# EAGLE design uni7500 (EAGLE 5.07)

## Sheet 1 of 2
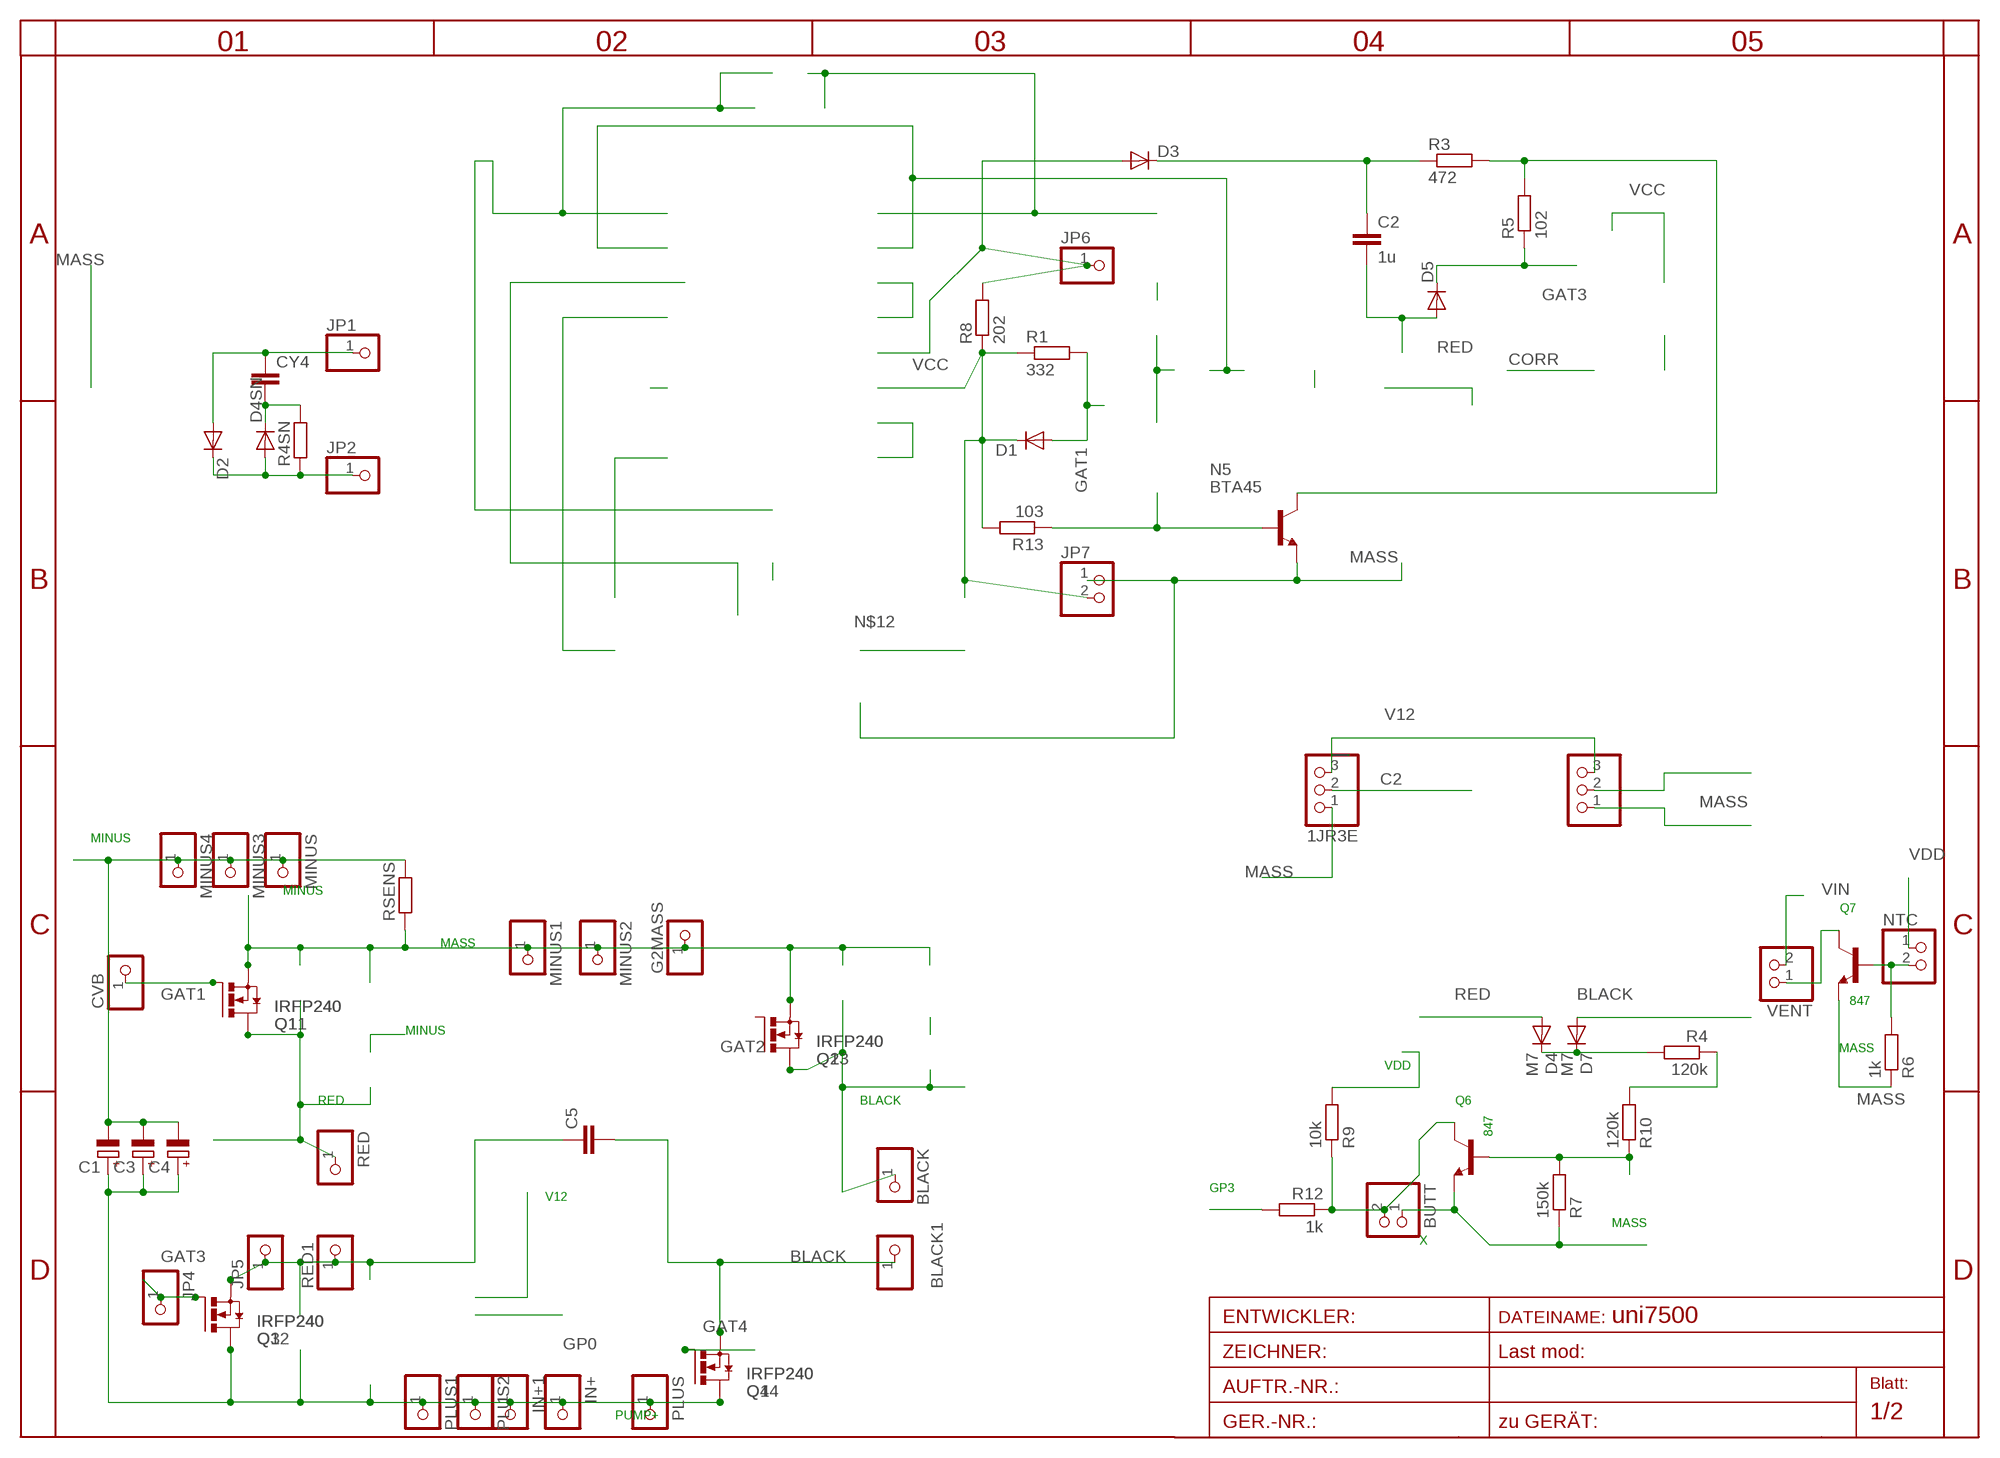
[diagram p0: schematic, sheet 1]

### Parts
1JR3E  PINHD-1X3  [1X03]
2JR4E3  PINHD-1X3  [1X03]
BLACK  PINHD-1X12MM3  [1X2MM3]
BLACK1  PINHD-1X12MM3  [1X2MM3]
BUTT  PINHD-1X2STR  [1X02]
C1  CPOL-EUE5-13  [E5-13]
C2  1u  C-EUC1206  [C1206]
C3  CPOL-EUE5-13  [E5-13]
C4  CPOL-EUE5-13  [E5-13]
C5  C-EU075-032X103  [C075-032X103]
CVB  PINHD-1X11MM0  [1X1MM0]
CY4  CXXC10B5  [XC10B5]
D1  DIODE-MINIMELF  [MINIMELF]
D2  DIODE-SMC  [SMC]
D3  DIODE-SMA-DO214  [SMA-DO214AC]
D4  M7  1N4004DO41-10  [DO41-10]
D4SN  DIODE-P1-10  [P1-10]
D5  DIODE-MINIMELF  [MINIMELF]
D7  M7  1N4004DO41-10  [DO41-10]
G2MASS  PINHD-1X11MM0  [1X1MM0]
IN+  PINHD-1X12MM3  [1X2MM3]
IN+1  PINHD-1X12MM3  [1X2MM3]
JP1  PINHD-1X11MM0  [1X1MM0]
JP2  PINHD-1X11MM0  [1X1MM0]
JP4  PINHD-1X11MM0  [1X1MM0]
JP5  PINHD-1X11MM0  [1X1MM0]
JP6  PINHD-1X11X0.4  [1X01]
JP7  PINHD-1X2STR  [1X02]
MINUS  PINHD-1X12MM3  [1X2MM3]
MINUS1  PINHD-1X12MM3  [1X2MM3]
MINUS2  PINHD-1X12MM3  [1X2MM3]
MINUS3  PINHD-1X12MM3  [1X2MM3]
MINUS4  PINHD-1X12MM3  [1X2MM3]
N5  BTA45  SMBTA45HV  [SOT23HV]
NTC  PINHD-1X2STR  [1X02]
PLUS  PINHD-1X12MM3  [1X2MM3]
PLUS1  PINHD-1X12MM3  [1X2MM3]
PLUS2  PINHD-1X12MM3  [1X2MM3]
Q1  IRFP240  [TO247BV]
Q2  IRFP240  [TO247BV]
Q3  IRFP240  [TO247BV]
Q4  IRFP240  [TO247BV]
Q6  847  BC847ALT1SMD  [SOT23]
Q7  847  BC847ALT1SMD  [SOT23]
Q11  IRFP240  [TO247BV]
Q12  IRFP240  [TO247BV]
Q13  IRFP240  [TO247BV]
Q14  IRFP240  [TO247BV]
R1  332  R-EU_R0805  [R0805]
R3  472  R-EU_R0805  [R0805]
R4  120k  R-EU_R1210  [R1210]
R4SN  R-EU_0207/10  [0207/10]
R5  102  R-EU_R1206  [R1206]
R6  1k  R-EU_R0805  [R0805]
R7  150k  R-EU_R0805  [R0805]
R8  202  R-EU_R0805  [R0805]
R9  10k  R-EU_R0805  [R0805]
R10  120k  R-EU_R1210  [R1210]
R12  1k  R-EU_R0805  [R0805]
R13  103  R-EU_0207/15  [0207/15]
RED  PINHD-1X12MM3  [1X2MM3]
RED1  PINHD-1X12MM3  [1X2MM3]
RSENS  R-EU_0204/7  [0204/7]
VENT  PINHD-1X2STR  [1X02]

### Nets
BLACK: BLACK1.1 BLACK.1 C5.2 D7.A Q2.D Q4.S Q13.D Q14.S
C1: 2JR4E3.2 ; also sheet 2
C2: 1JR3E.2 D1.C JP7.2 R1.1 R8.1 R13.2 ; also sheet 2
DRAIN: D2.C D4SN.A JP2.1 R4SN.1
GAT1: CVB.1 D1.A Q1.G Q11.G R1.2
GAT2: Q2.G Q13.G
GAT3: D5.C JP4.1 Q3.G Q12.G R5.1
GAT4: Q4.G Q14.G
GP3: R12.2 ; also sheet 2
MASS: 1JR3E.1 2JR4E3.1 BUTT.1 G2MASS.1 JP7.1 MINUS1.1 MINUS2.1 N5.2(E) Q1.S Q2.S Q6.2(E) Q7.2(E) Q11.S Q13.S R6.1 R7.1 RSENS.1 ; also sheet 2
MINUS: C1.- C3.- C4.- MINUS3.1 MINUS4.1 MINUS.1 RSENS.2
N$1: D4.C D7.C R4.2
N$4: C2.1 D3.K(C) R3.1
N$5: Q6.1(B) R7.2 R10.1
N$7: R4.1 R10.2
N$8: N5.3(C) R3.2 R5.2
N$9: NTC.2 Q7.1(B) R6.2
N$10: Q7.3(C) VENT.1
N$17: N5.1(B) R13.1
PUMP+: C1.+ C3.+ C4.+ IN+1.1 IN+.1 PLUS1.1 PLUS2.1 PLUS.1 Q3.D Q4.D Q12.D Q14.D ; also sheet 2
RED: C2.2 C5.1 D4.A D5.A JP5.1 Q1.D Q3.S Q11.D Q12.S RED1.1 RED.1
SNUB2: CY4.2 D4SN.C R4SN.2
SOURCE: CY4.1 D2.A JP1.1
V12: 1JR3E.3 2JR4E3.3
VCC: D3.A JP6.1 R8.2
VDD: NTC.1 R9.2 ; also sheet 2
VIN: VENT.2
X: BUTT.2 Q6.3(C) R9.1 R12.1

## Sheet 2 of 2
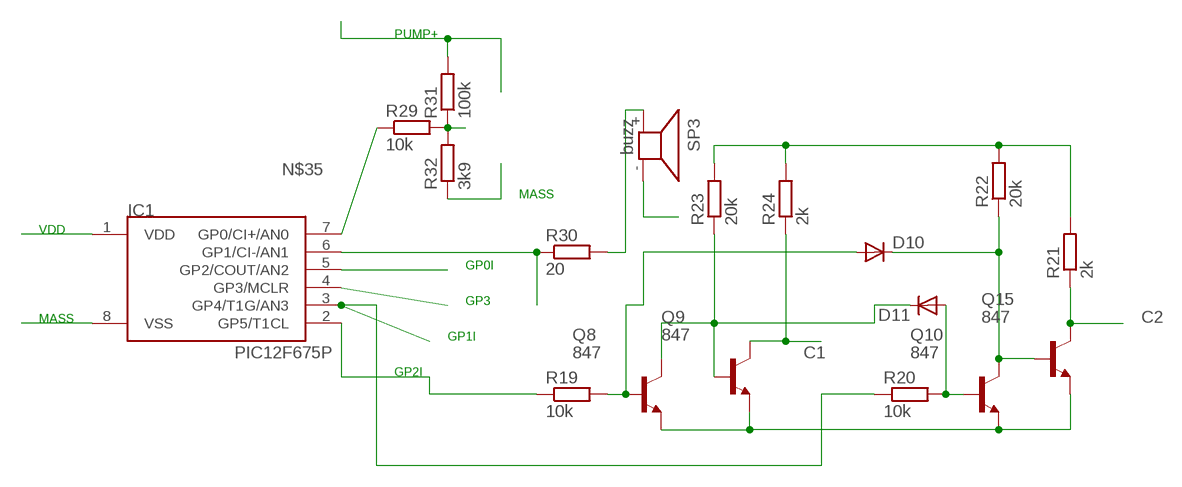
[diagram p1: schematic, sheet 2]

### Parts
D10  DIODE-MINIMELF  [MINIMELF]
D11  DIODE-MINIMELF  [MINIMELF]
IC1  PIC12F675P  [DIL8]
Q8  847  BC847ALT1SMD  [SOT23]
Q9  847  BC847ALT1SMD  [SOT23]
Q10  847  BC847ALT1SMD  [SOT23]
Q15  847  BC847ALT1SMD  [SOT23]
R19  10k  R-EU_R0805  [R0805]
R20  10k  R-EU_R0805  [R0805]
R21  2k  R-EU_R0805  [R0805]
R22  20k  R-EU_R0805  [R0805]
R23  20k  R-EU_R0805  [R0805]
R24  2k  R-EU_R0805  [R0805]
R29  10k  R-EU_R0805  [R0805]
R30  20  R-EU_R0805  [R0805]
R31  100k  R-EU_0207/25  [0207/25]
R32  3k9  R-EU_R0805  [R0805]
SP3  buzz  KSS12017MM  [KSS1202]

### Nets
C1: Q9.3(C) R24.1 ; also sheet 1
C2: Q15.3(C) R21.1 ; also sheet 1
GP0I: IC1.5(GP2/COUT/AN2)
GP1I: IC1.3(GP4/T1G/AN3) R20.1
GP2I: IC1.2(GP5/T1CL) R19.1
GP3: IC1.4(GP3/MCLR) ; also sheet 1
MASS: IC1.8(VSS) R32.1 SP3.- ; also sheet 1
N$22: D11.A Q10.1(B) R20.2
N$24: R30.2 SP3.+
N$26: D11.C Q8.3(C) Q9.1(B) R23.1
N$27: D10.C Q10.3(C) Q15.1(B) R22.1
N$28: D10.A Q8.1(B) R19.2
N$30: Q8.2(E) Q9.2(E) Q10.2(E) Q15.2(E)
N$31: IC1.6(GP1/CI-/AN1) R30.1
N$32: R21.2 R22.2 R23.2 R24.2
N$34: R29.2 R31.1 R32.2
N$35: IC1.7(GP0/CI+/AN0) R29.1
PUMP+: R31.2 ; also sheet 1
VDD: IC1.1(VDD) ; also sheet 1

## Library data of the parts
1JR3E 2JR4E3 = pinhead:PINHD-1X3: PIN HEADER
BLACK BLACK1 CVB G2MASS IN+ IN+1 JP1 JP2 JP4-JP6 MINUS MINUS1-MINUS4 PLUS PLUS1 PLUS2 RED RED1 = pinhead:PINHD-1X1: PIN HEADER
BUTT JP7 NTC VENT = pinhead:PINHD-1X2: PIN HEADER
C1 C3 C4 = rcl:CPOL-EU: POLARIZED CAPACITOR, European symbol
C2 C5 = rcl:C-EU: CAPACITOR, European symbol
CY4 = rcl:CX: X CAPACITOR
D1-D3 D4SN D5 D10 D11 = diode:DIODE-: DIODE
D4 D7 = diode:1N4004: DIODE
IC1 = microchip-5:PIC12F6*: uPC nW 1k Program Flash memory 2x Timer Comparator 10b A/D converter/ 4xIN
N5 = transistor-npn:SMBTA45
Q1-Q4 Q11-Q14 = transistor-power:IRFP240: HEXFET Power MosFet Source: http://www.irf.com/
Q6-Q10 Q15 = transistor-npn:BC847*: NPN Transistor
R1 R3 R4 R4SN R5-R10 R12 R13 RSENS = rcl:R-EU_: RESISTOR, European symbol
R19-R24 R29-R32 = rcl-2:R-EU_: RESISTOR, European symbol
SP3 = buzzer:KSS1201: SPEAKER

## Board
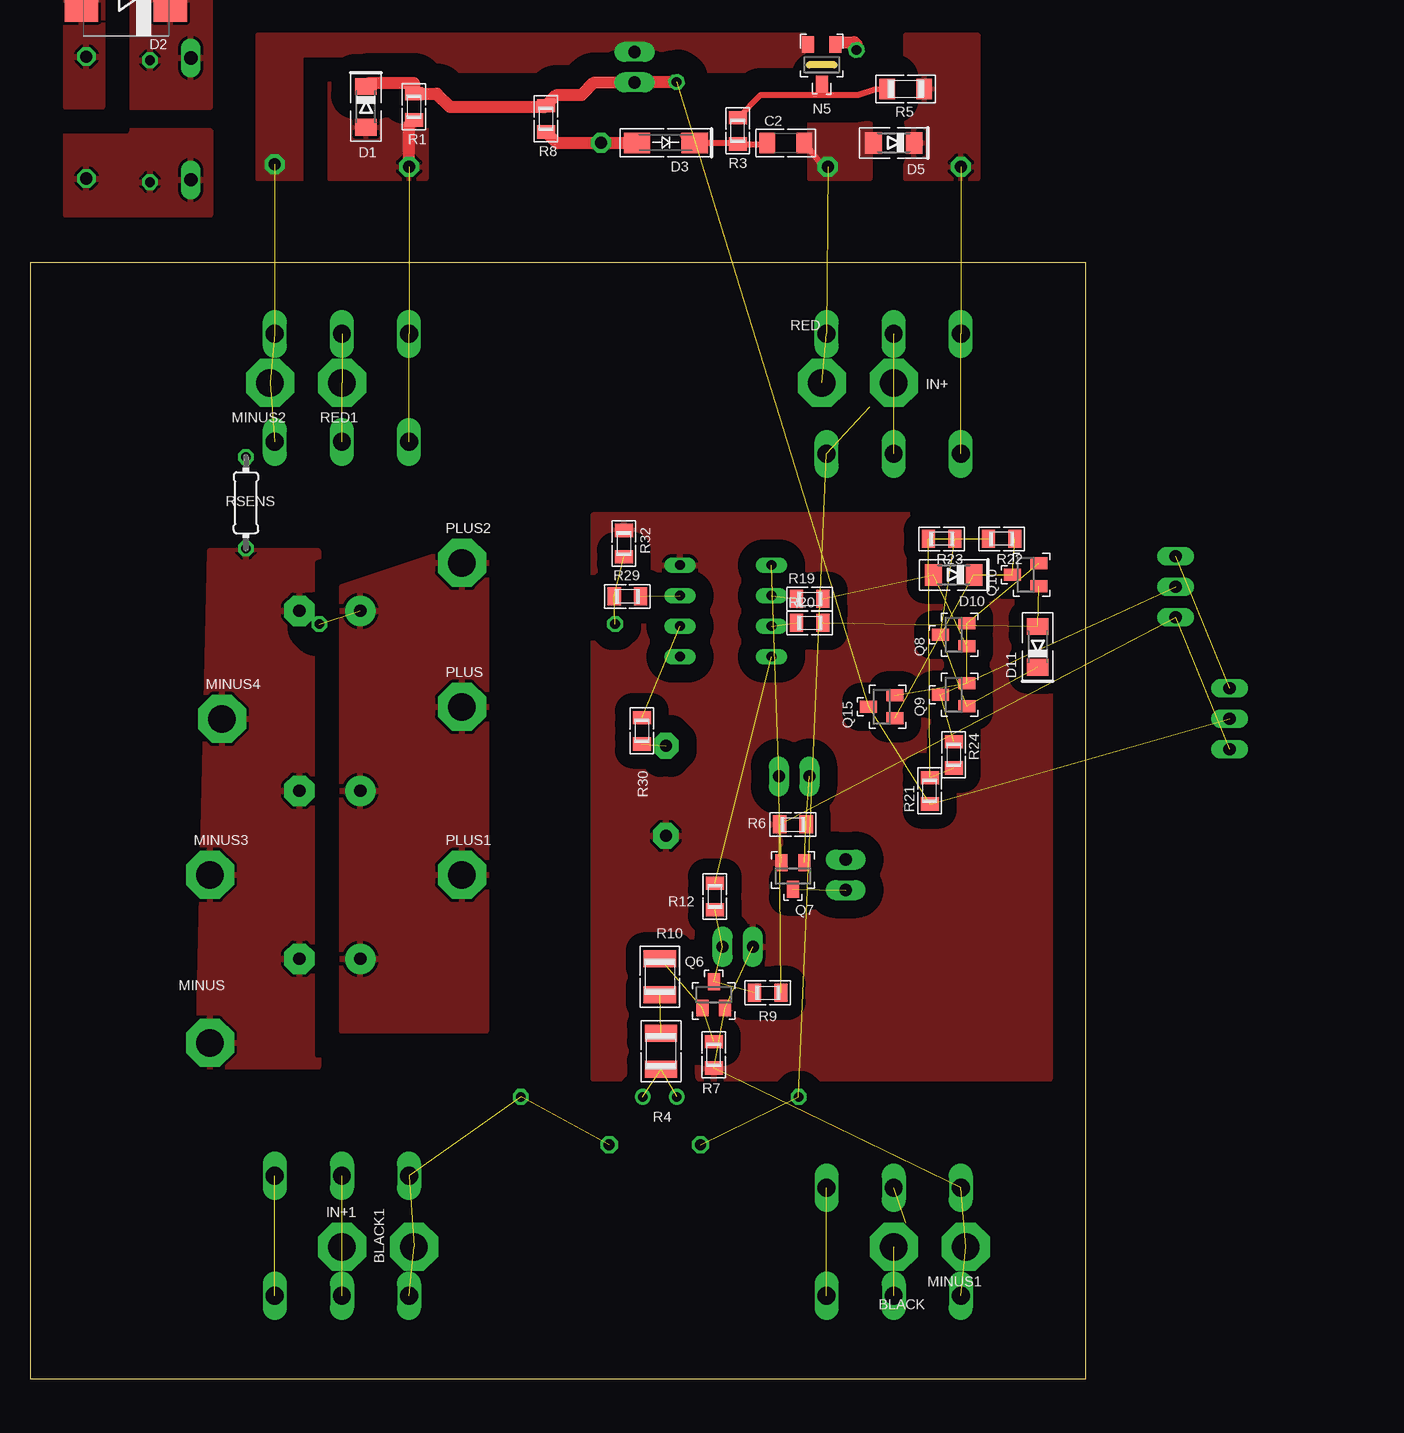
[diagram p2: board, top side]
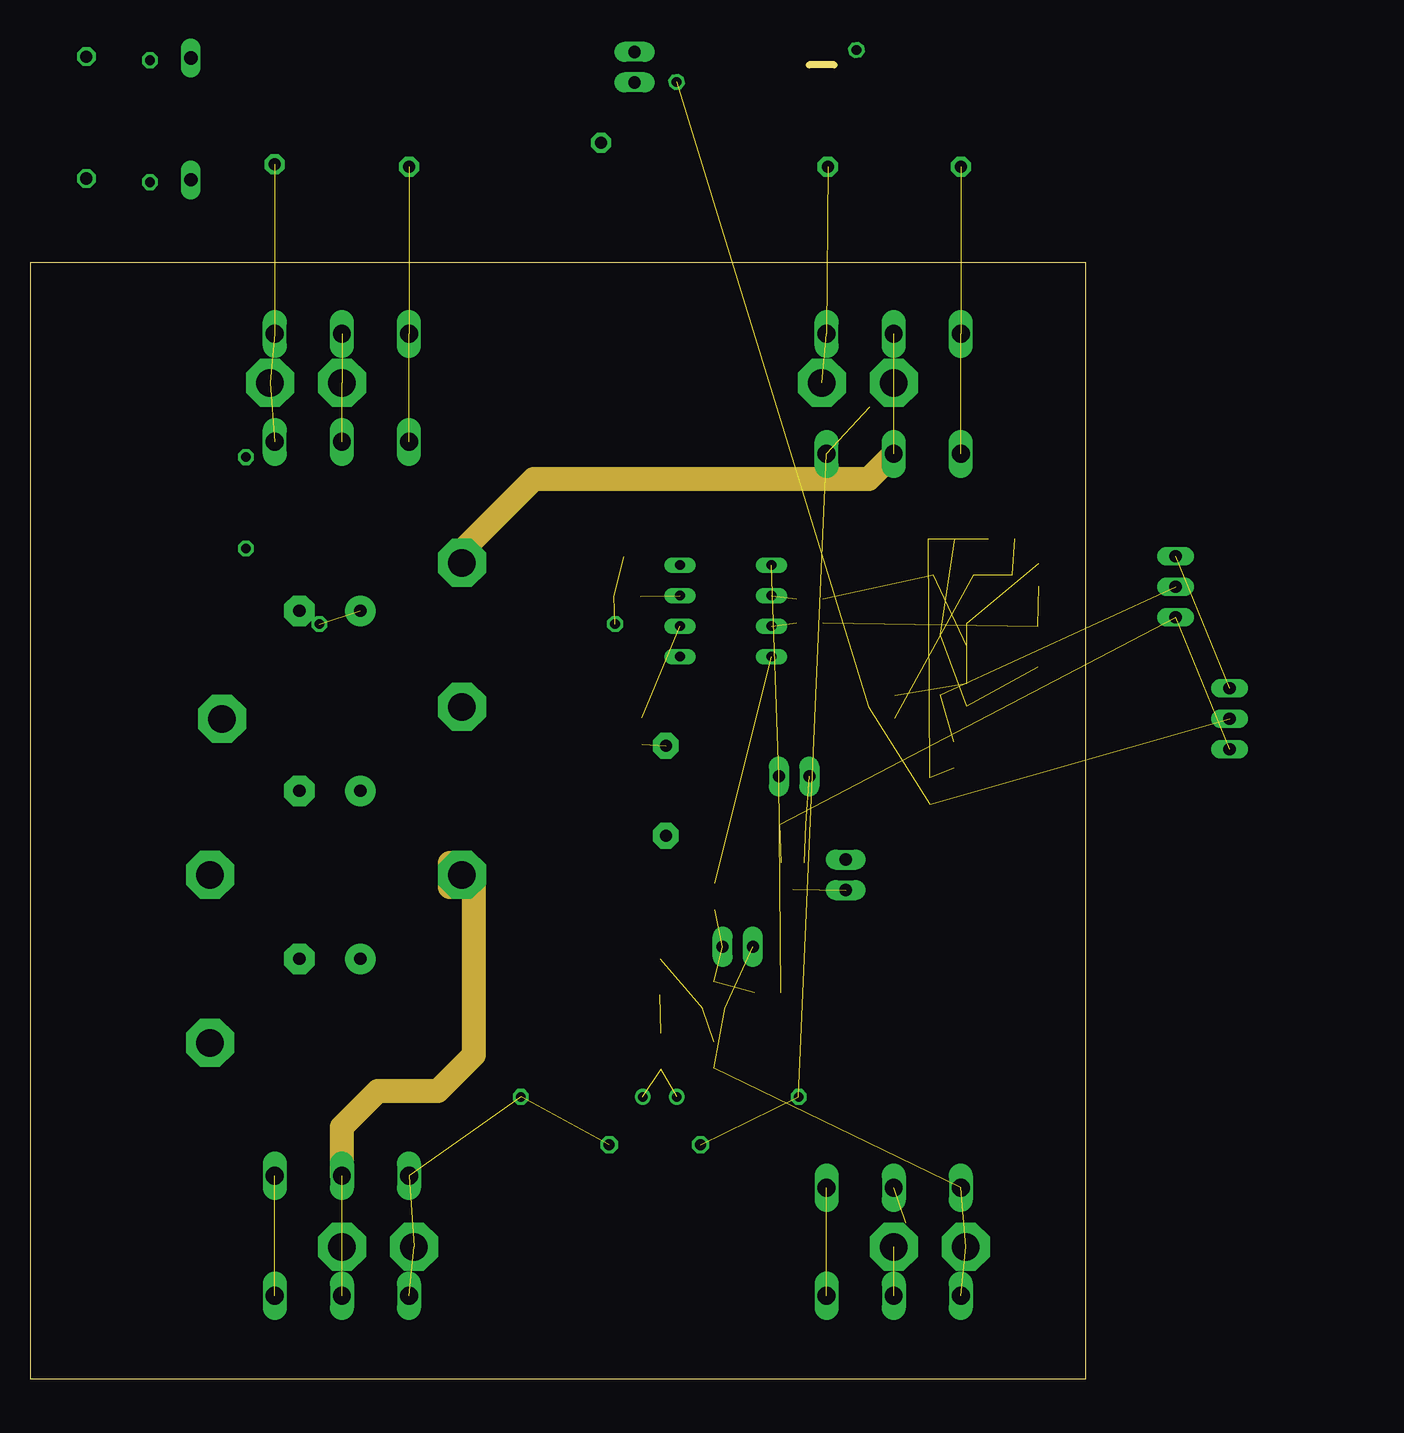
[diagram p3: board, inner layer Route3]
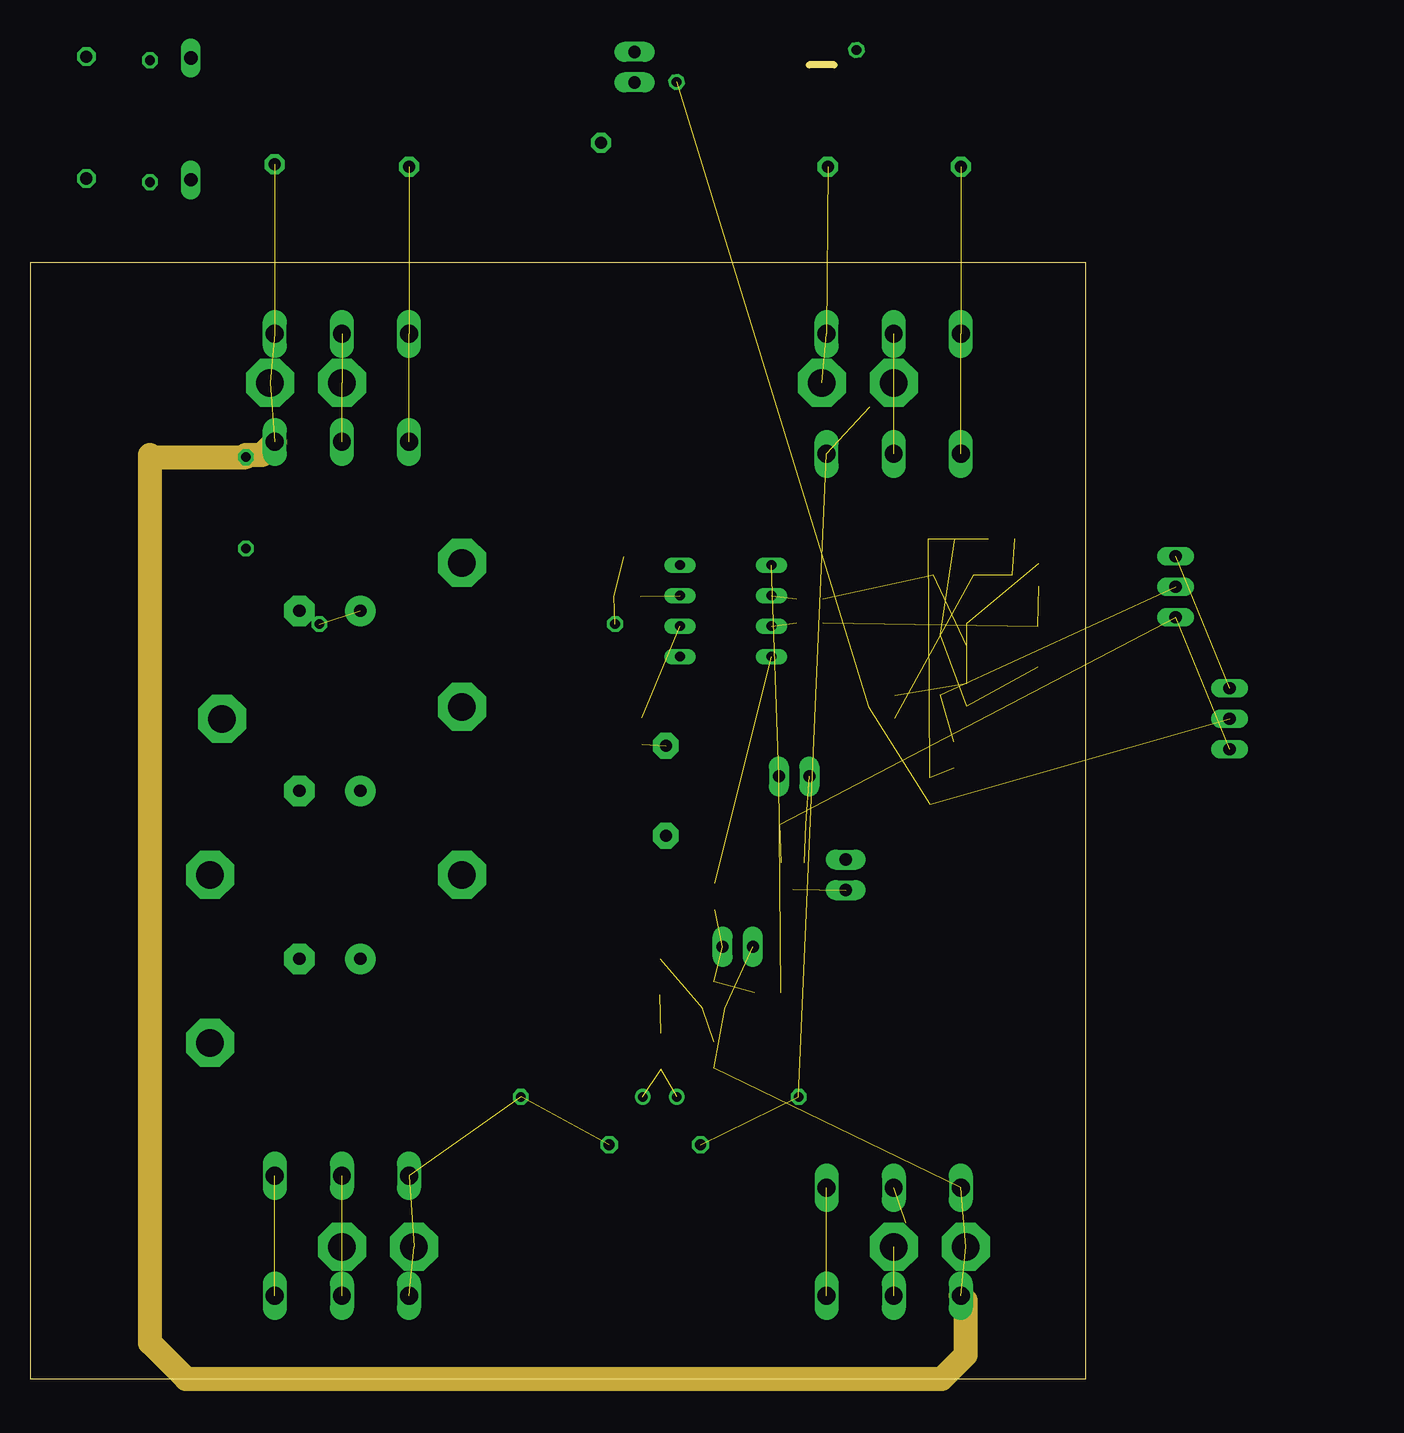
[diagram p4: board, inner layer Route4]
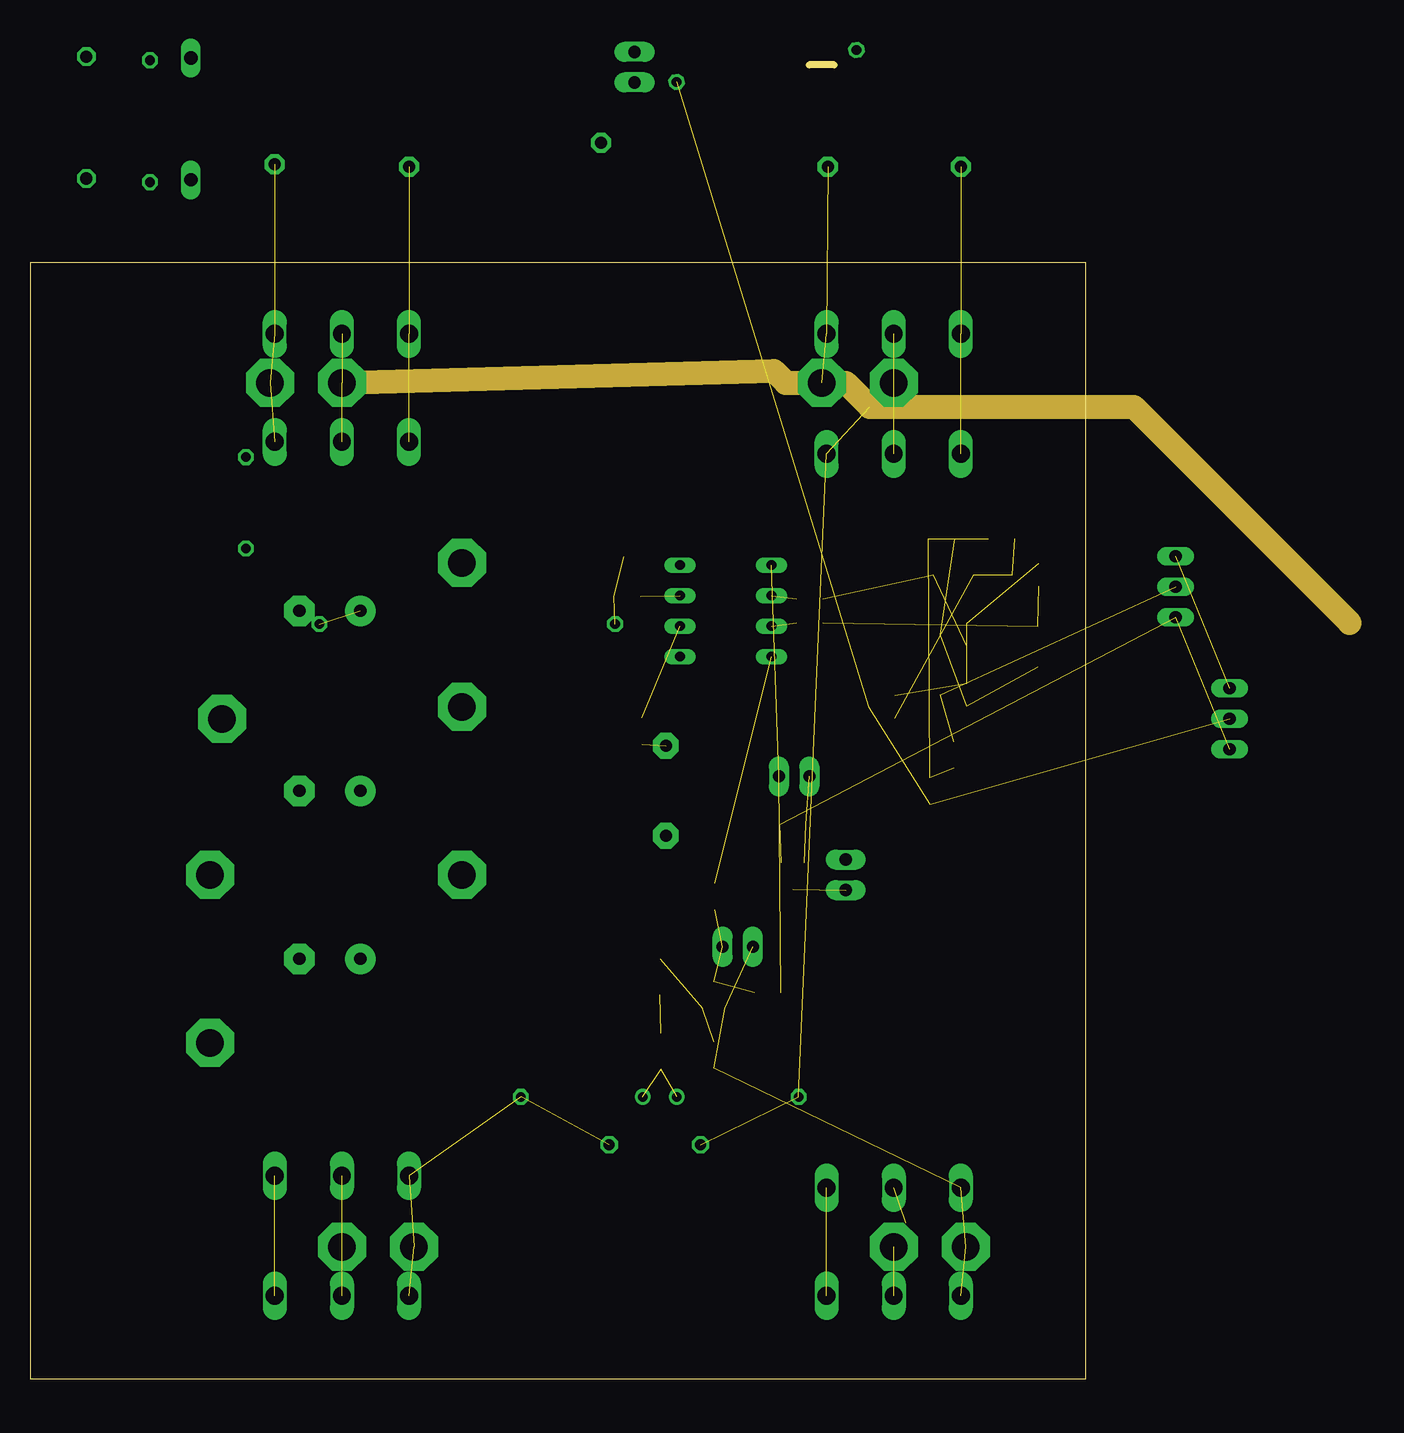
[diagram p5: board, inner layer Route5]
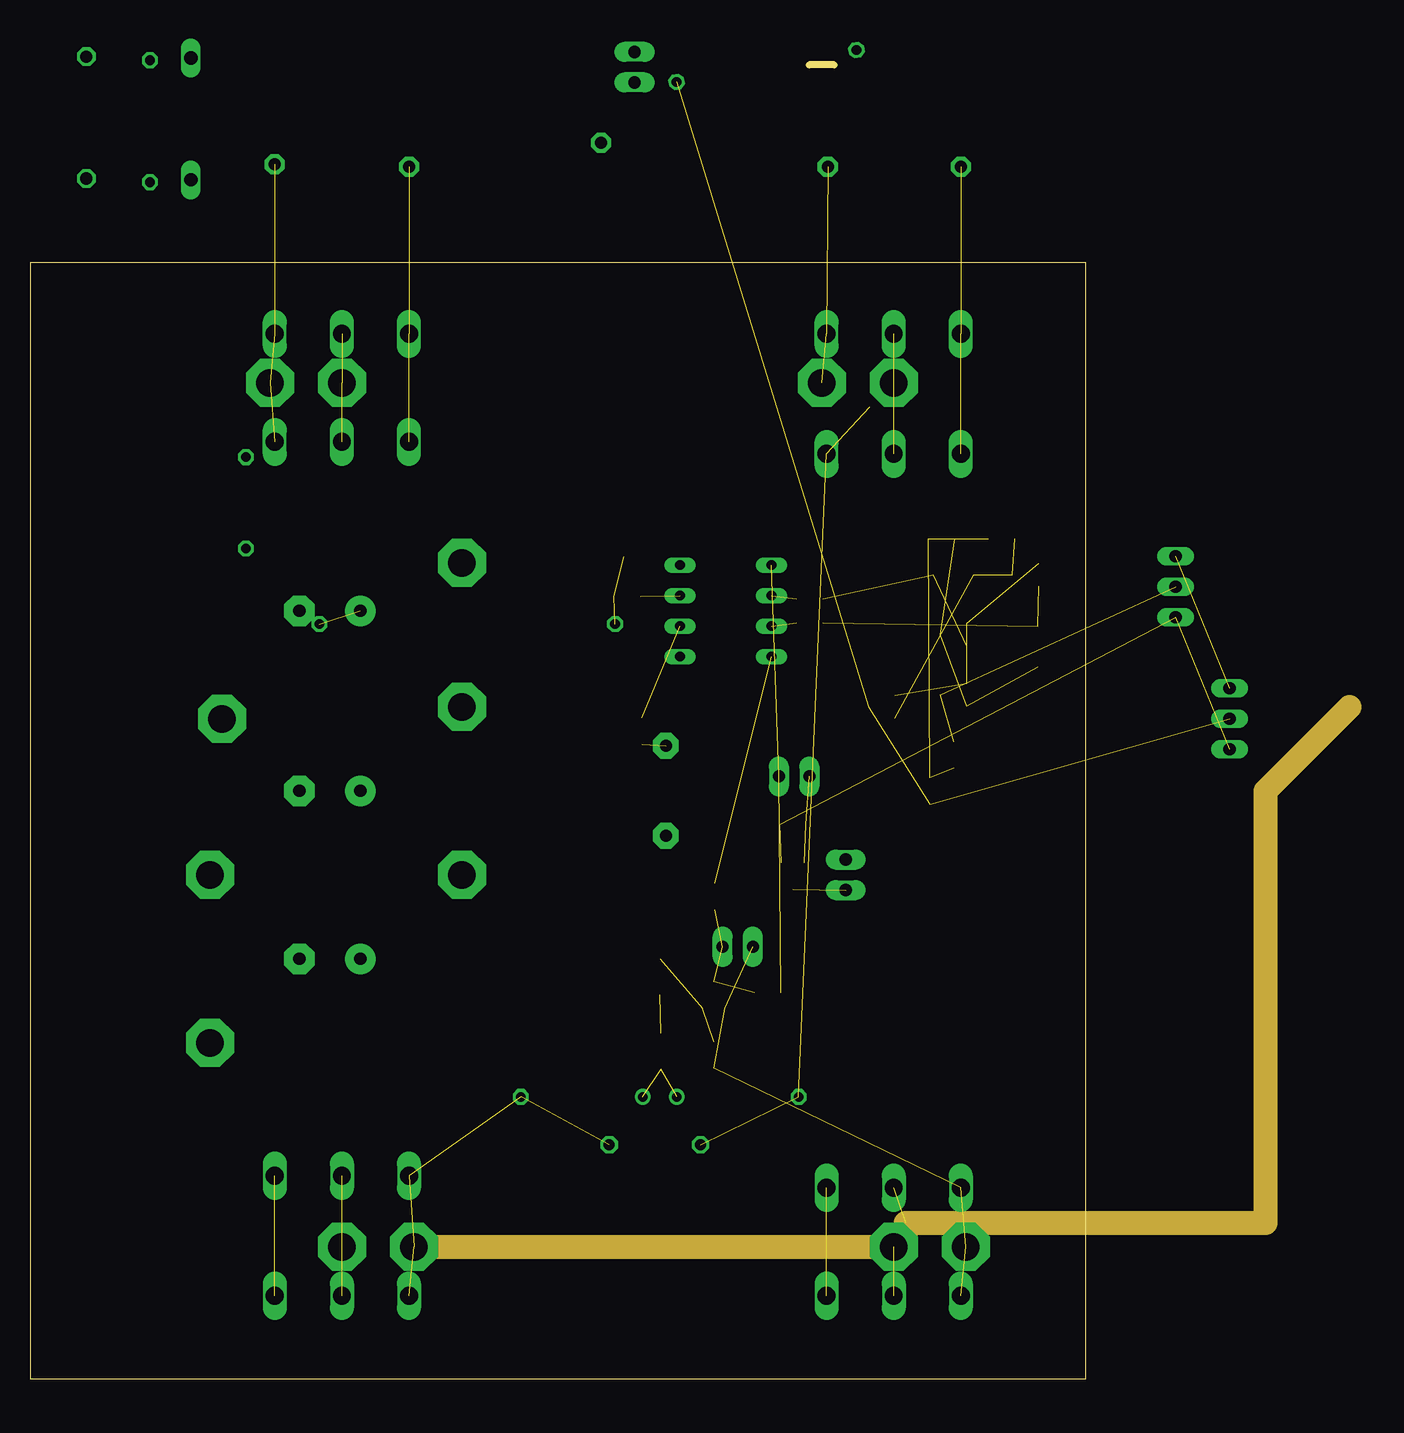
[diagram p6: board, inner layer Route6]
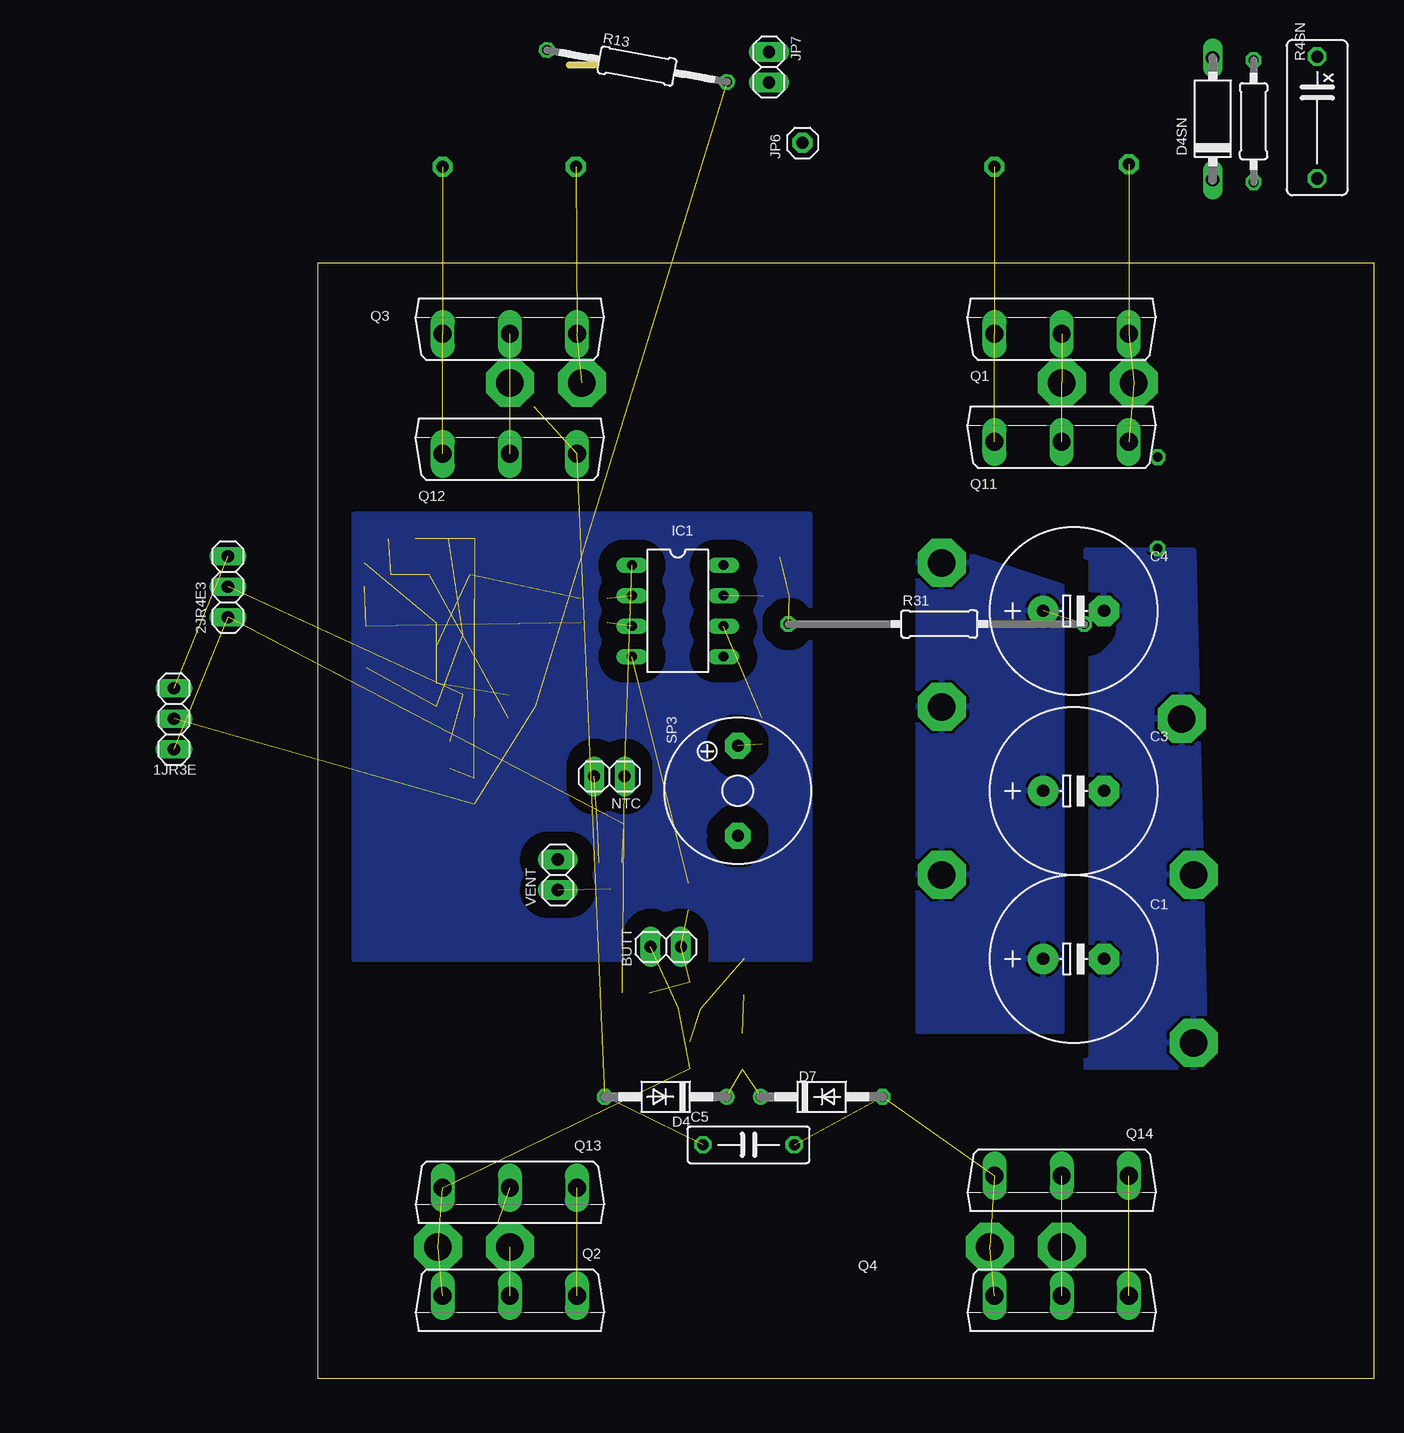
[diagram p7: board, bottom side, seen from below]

Size 88 x 93 mm. Coordinates in mm from the lower left corner, seen from the top.
Outline: 0,0 88,0 88,93 0,93 0,0
Copper layers (1*16): Top 0.035mm / dielectric 1.5mm / Bottom 0.035mm
Design rules "default *": minimum track width 10mil, minimum drill 20mil, track to track 8mil, track to pad 8mil, pad to pad 8mil, via to via 8mil, smd to smd 8mil, copper to edge 40mil, drill to drill 8mil, minimum pad ring 10mil, minimum via ring 8mil, stop-mask expansion 4mil, vias tented up to drill 0mil, thermal gap 10mil

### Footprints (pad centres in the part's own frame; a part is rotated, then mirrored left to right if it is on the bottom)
1X03 = drill 1.016 long: 1 -2.54,0; 2 0,0; 3 2.54,0
1X2MM3 = drill 2.3 pad 4 octagon: 1 0,0
1X02 = drill 1.016 pad 1.676 long: 1 -1.27,0; 2 1.27,0
E5-13 = drill 1.016 pad 2.54 round: + -2.54,0 | drill 1.016 pad 2.54 octagon: - 2.54,0
C1206 = smd 1.3 x 1.7: 1 -1.55,0; 2 1.55,0
C075-032X103 = drill 0.914 octagon: 1 -3.81,0; 2 3.81,0
1X1MM0 = drill 1 pad 1.676 octagon: 1 0,0
XC10B5 = drill 1.016 octagon: 1 -5.08,0; 2 5.08,0
MINIMELF = smd 1.4 x 1.8: A 1.7,0; C -1.7,0
SMC = smd 2.8 x 3.8: A 3.7,0; C -3.7,0
SMA-DO214AC = smd 2.2 x 1.7: A 2.4,0; K -2.4,0
DO41-10 = drill 0.8 octagon: A 5.08,0 | drill 0.8 round: C -5.08,0
P1-10 = drill 1.118 long: A 5.08,0; C -5.08,0
DIL8 = drill 0.8 long: 1 -3.81,-3.81; 2 -1.27,-3.81; 3 1.27,-3.81; 4 3.81,-3.81; 5 3.81,3.81; 6 1.27,3.81; 7 -1.27,3.81; 8 -3.81,3.81
1X01 = drill 1 pad 1.676 octagon: 1 0,0
SOT23HV = smd 1 x 1.4: 1 -1.15,-1.7; 2 1.15,-1.7; 3 0,1.6
TO247BV = drill 1.499 long: D 0,-2.921; G -5.588,-2.921; S 5.588,-2.921
SOT23 = smd 1 x 1.4: 1 -0.95,-1.1; 2 0.95,-1.1; 3 0,1.1
R0805 = smd 1.1 x 1.5: 1 -1.1,0; 2 1.1,0
R1210 = smd 1.4 x 2.7: 1 -1.5,0; 2 1.5,0
0207/10 = drill 0.813 octagon: 1 -5.08,0; 2 5.08,0
R1206 = smd 1.3 x 1.7: 1 -1.55,0; 2 1.55,0
0207/15 = drill 0.813 octagon: 1 -7.62,0; 2 7.62,0
0207/25 = drill 0.813 octagon: 1 -12.58,0; 2 12.08,0
0204/7 = drill 0.813 octagon: 1 -3.81,0; 2 3.81,0
KSS1202 = drill 1 pad 2.159 octagon: + 3.75,0; - -3.75,0

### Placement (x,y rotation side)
1JR3E  not placed on the board
2JR4E3  not placed on the board
BLACK  72,11 180 top
BLACK1  32,11 90 top
BUTT  59,36 0 bottom
C1  25,35 0 bottom
C2  63,103 0 top  (outside the outline)
C3  25,49 0 bottom
C4  25,64 0 bottom
C5  52.1,19.5 0 bottom
CVB  31.6,101 0 top  (outside the outline)
CY4  not placed on the board
D1  28,106 270 top  (outside the outline)
D2  not placed on the board
D3  53,103 180 top  (outside the outline)
D4  59,23.5 180 bottom
D4SN  not placed on the board
D5  not placed on the board
D7  46,23.5 0 bottom
D10  77,67 180 top
D11  84,61 90 top
G2MASS  not placed on the board
IC1  58,64 270 bottom
IN+  72,83 0 top
IN+1  26,11 0 top
JP1  not placed on the board
JP2  not placed on the board
JP4  not placed on the board
JP5  66.5,101 180 top  (outside the outline)
JP6  47.6,103 90 bottom  (outside the outline)
JP7  50.4,109.3 270 bottom  (outside the outline)
MINUS  15,28 0 top
MINUS1  78,11 180 top
MINUS2  20,83 180 top
MINUS3  15,42 0 top
MINUS4  16,55 0 top
N5  66,109.5 180 top  (outside the outline)
NTC  63.7,50.2 180 bottom
PLUS  36,56 0 top
PLUS1  36,42 0 top
PLUS2  36,68 0 top
Q1  26,90 0 bottom
Q2  72,4 180 bottom
Q3  72,90 0 bottom
Q4  26,4 180 bottom
Q6  57,32 0 top
Q7  63.6,41.9 180 top
Q8  77,62 90 top
Q9  77,57 90 top
Q10  83,67 90 top
Q11  26,81 0 bottom
Q12  72,80 0 bottom
Q13  72,13 180 bottom
Q14  26,14 180 bottom
Q15  71,56 90 top
R1  32,106 270 top  (outside the outline)
R3  59,104 90 top  (outside the outline)
R4  52.6,27.3 270 top
R4SN  not placed on the board
R5  73,107.5 180 top  (outside the outline)
R6  63.6,46.2 0 top
R7  57,27 90 top
R8  43,105 270 top  (outside the outline)
R9  61.5,32.17 0 top
R10  52.5,33.5 270 top
R12  57.1,40.2 90 top
R13  61.4,109.4 350 bottom  (outside the outline)
R19  65,65 0 top
R20  65,63 0 top
R21  75,49 90 top
R22  81,70 180 top
R23  76,70 180 top
R24  77,52 270 top
R29  49.8,65.2 180 top
R30  51,54 270 top
R31  36.2,62.9 0 bottom
R32  49.5,69.6 270 top
RED  66,83 0 top
RED1  26,83 180 top
RSENS  18,73 270 top
SP3  53,49 90 bottom
VENT  68,42 90 bottom

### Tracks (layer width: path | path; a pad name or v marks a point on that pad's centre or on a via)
BLACK  (6 unrouted)
  Route6 2: BLACK1.1 BLACK.1 73,12 73,13 103,13 103,49 110,56
C1  (2 unrouted)
C2  (3 unrouted)
  Top 1: R13.2 50.45,108.08 JP7.2 47.03,108.03 46,107 43.9,107 R8.1 42.9,106 35,106 33.9,107.1 R1.1 32,108 28.3,108 D1.C
DRAIN
  pour Top (isolate 2, rank 2): 8,120 8,106 15,106 15,120
GAT1  (2 unrouted)
  Top 1: R1.2 31.6,104.5 CVB.1
  pour Top (isolate 2): 25,100 25,108 33,108 33,100
GAT2  (1 unrouted)
GAT3  (2 unrouted)
  pour Top (isolate 2, rank 2): 73,112 79,112 79,100 73,100
GAT4  (1 unrouted)
GP1I  (1 unrouted)
GP2I  (1 unrouted)
GP3  (1 unrouted)
MASS  (11 unrouted)
  Route4 2: Q11.S 19.33,77 18,77 RSENS.1 10.19,76.81 10,77 10,3 13,0 76,0 78,2 78,6.51 Q2.S
  pour Top (isolate 1.5): 47,72 85,72 85,25 47,25
  pour Top (isolate 2, rank 2, no thermals): 19,112 65,112 65,109 23,109 23,100 19,100
MINUS
  pour Top (isolate 2, rank 2): 15,69 24,69 24,26 14,26
  pour Bottom (isolate 2, rank 2): 15,69 24,69 24,26 14,26
N$1  (2 unrouted)
N$4
  Top 0.5: C2.1 61.8,102.9 R3.1 58.9,103 55,103 54.4,103.6 D3.K
N$5  (2 unrouted)
N$7  (1 unrouted)
N$8
  Top 0.5: R5.2 70.45,107.45 69,107 66,107 | R3.2 60.9,107 66,107 | 66,107 N5.3
N$9  (2 unrouted)
N$10  (1 unrouted)
N$17
  Top 1: N5.1 67.35,111.4 68.7,111.4 68.9,111.2 R13.1
N$22  (2 unrouted)
N$24  (1 unrouted)
N$26  (3 unrouted)
N$27  (3 unrouted)
N$28  (2 unrouted)
N$30  (3 unrouted)
N$31  (1 unrouted)
N$32  (3 unrouted)
N$34  (2 unrouted)
N$35  (1 unrouted)
PUMP+  (5 unrouted)
  Route3 2: PLUS2.1 36,69 42,75 69.92,75 Q12.D | Q14.D 26,21 29,24 34,24 37,27 37,41 PLUS1.1 | PLUS1.1 35,43 35,42 | 35,42 35,41 | PLUS1.1 35,42
  pour Top (isolate 2): 26,66 38,70 38,29 26,29
  pour Bottom (isolate 2): 26,66 38,70 38,29 26,29
RED  (7 unrouted)
  Top 0.5: C2.2 66.1,101 JP5.1 67,101
  Route5 2: RED1.1 62,84 63,83 RED.1 68,83 70,81 92,81 110,63
  pour Top (isolate 2, no thermals): 65,105 70,105 70,100 65,100
SNUB2
  pour Top (isolate 2, rank 2): 3,104 15,104 15,97 3,97
SOURCE
  pour Top (isolate 2): 3,120 6,120 6,106 3,106
V12  (1 unrouted)
  pour Bottom (isolate 1.5): 47,72 85,72 85,35 47,35
VCC
  Top 1: D3.A JP6.1 43.9,103 R8.2
VDD  (2 unrouted)
X  (3 unrouted)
